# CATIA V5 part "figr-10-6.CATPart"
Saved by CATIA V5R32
Part number: Part1
Bounding box of the stored display mesh (mm): x -9.888 to 10, y -9.972 to 9.972, z 0 to 10
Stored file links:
  D:\PROJECTS\Project 2022\CATIA V5 6R 2022\Resources\Part Files\c10_catia_v5_6r2022_prt\c10_catia_v5_6r2022_prt\figr-10-6.CATPart
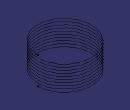
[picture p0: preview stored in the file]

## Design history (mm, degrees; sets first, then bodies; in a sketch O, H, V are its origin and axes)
Set1
  Helix1: Direction {line stored without definition}, RefPoint {point type Coord, X 10, Y 0, Z 0}, Pitch 1, Height 10, TaperAngle 0
Body1 (main body)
